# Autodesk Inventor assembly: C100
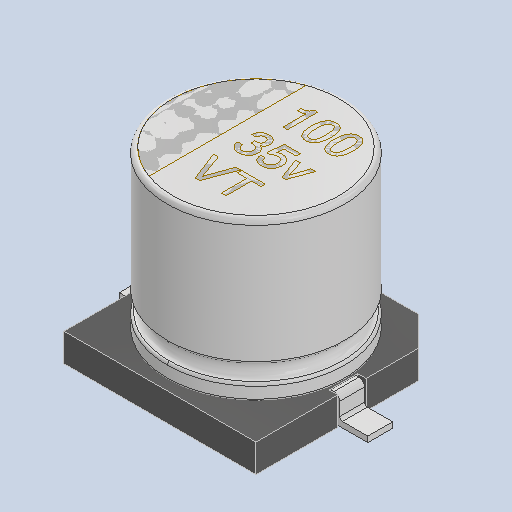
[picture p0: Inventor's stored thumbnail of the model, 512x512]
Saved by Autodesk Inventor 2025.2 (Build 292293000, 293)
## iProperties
Created: 2025-04
Part Number: C100
Description: PART--DESC
Document SubType Name: Assembly
Designer: BennF
Author: BennF
Revision Number: NONE
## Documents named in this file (4)
- C:\Users\BennF\Nextcloud\Benutzer\CNC JarBeRi\existing parts\Electronics\RepRap A4988 Shied (USE WITHOUT ARDUINO)\reprap-a4988-1.snapshot.1\RepRap\RepRap\C100_1.iam
- C:\Users\BennF\Nextcloud\Benutzer\CNC JarBeRi\existing parts\Electronics\RepRap A4988 Shied (USE WITHOUT ARDUINO)\reprap-a4988-1.snapshot.1\RepRap\RepRap\C100 Geometry.ipt
- C:\Users\BennF\Nextcloud\Benutzer\CNC JarBeRi\existing parts\Electronics\RepRap A4988 Shied (USE WITHOUT ARDUINO)\reprap-a4988-1.snapshot.1\RepRap\RepRap\name3.ipt
- C:\Users\BennF\Nextcloud\Benutzer\CNC JarBeRi\existing parts\Electronics\RepRap A4988 Shied (USE WITHOUT ARDUINO)\reprap-a4988-1.snapshot.1\RepRap\RepRap\bay_1.iam
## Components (3 placed, 3 different names)
1. C100 Geometry
2. name3
3. bay [sub-assembly]
